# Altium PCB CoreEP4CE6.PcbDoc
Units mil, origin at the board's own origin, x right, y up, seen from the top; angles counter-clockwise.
Board outline 6000 x 4000 mil, 2 copper layers (Top Layer, Bottom Layer); 3 components, 0 nets, 98 pads, 0 vias.
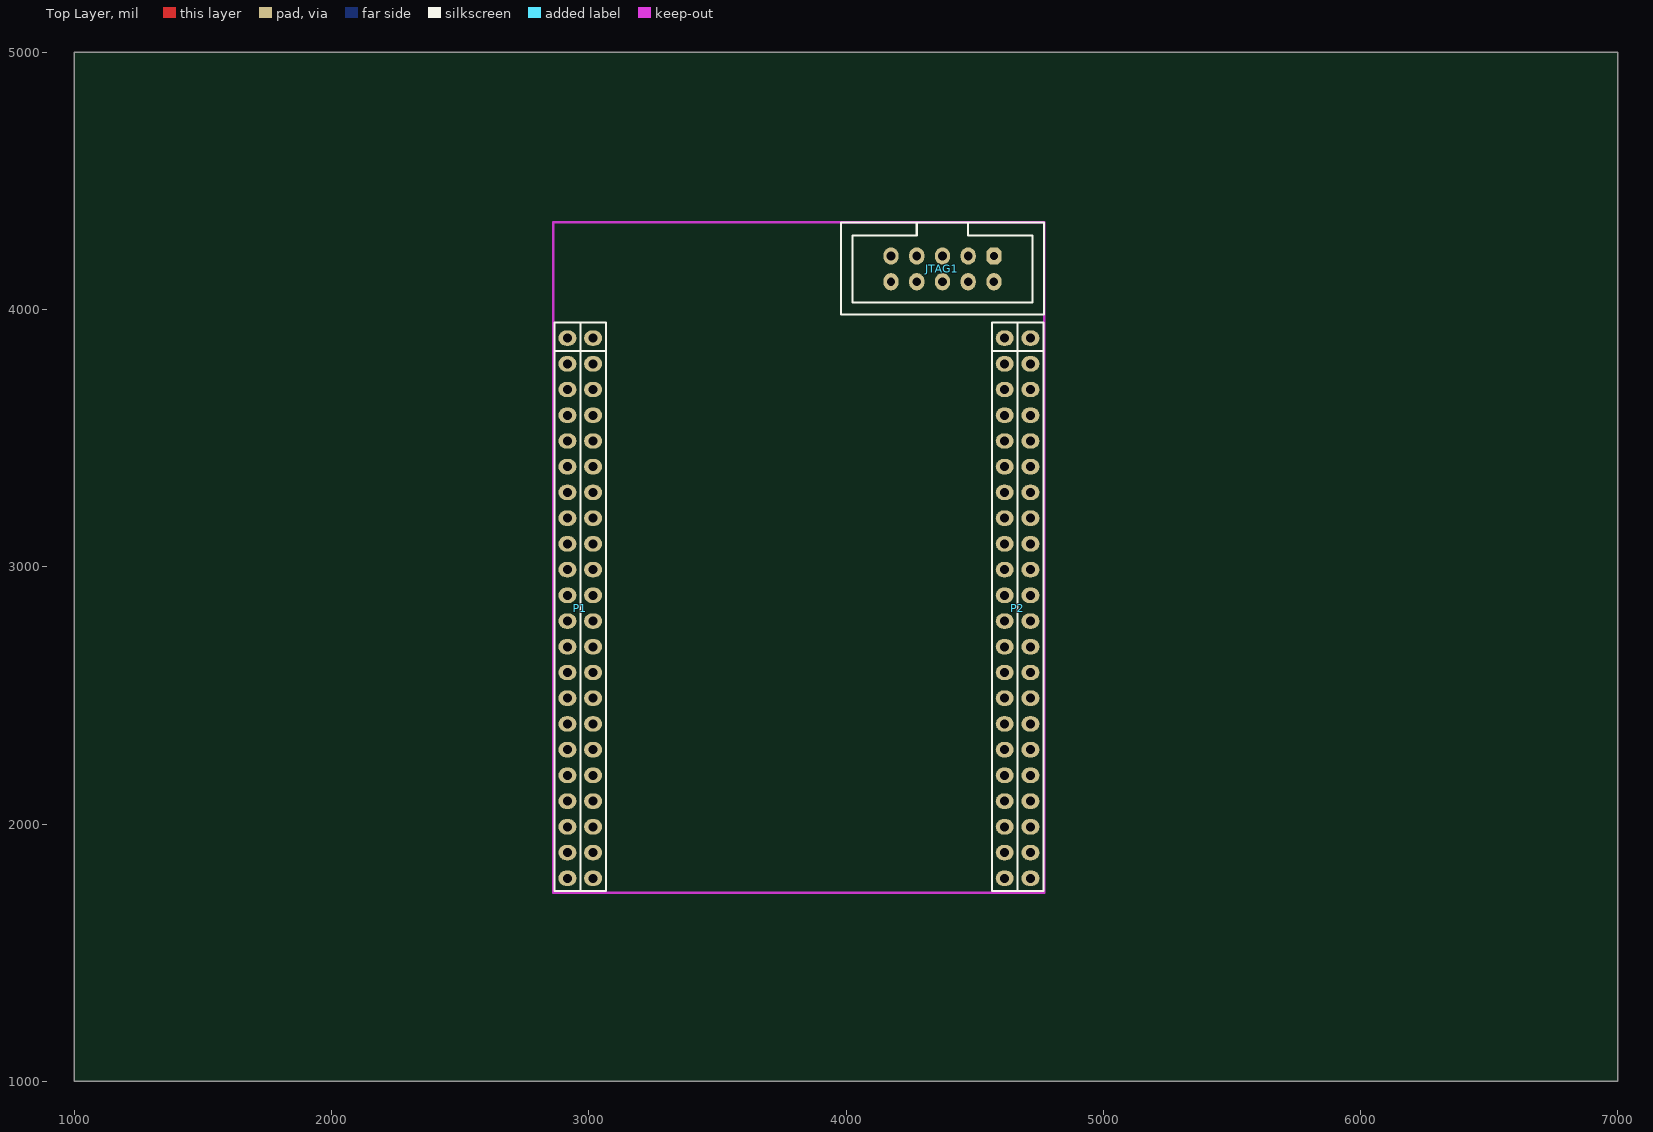
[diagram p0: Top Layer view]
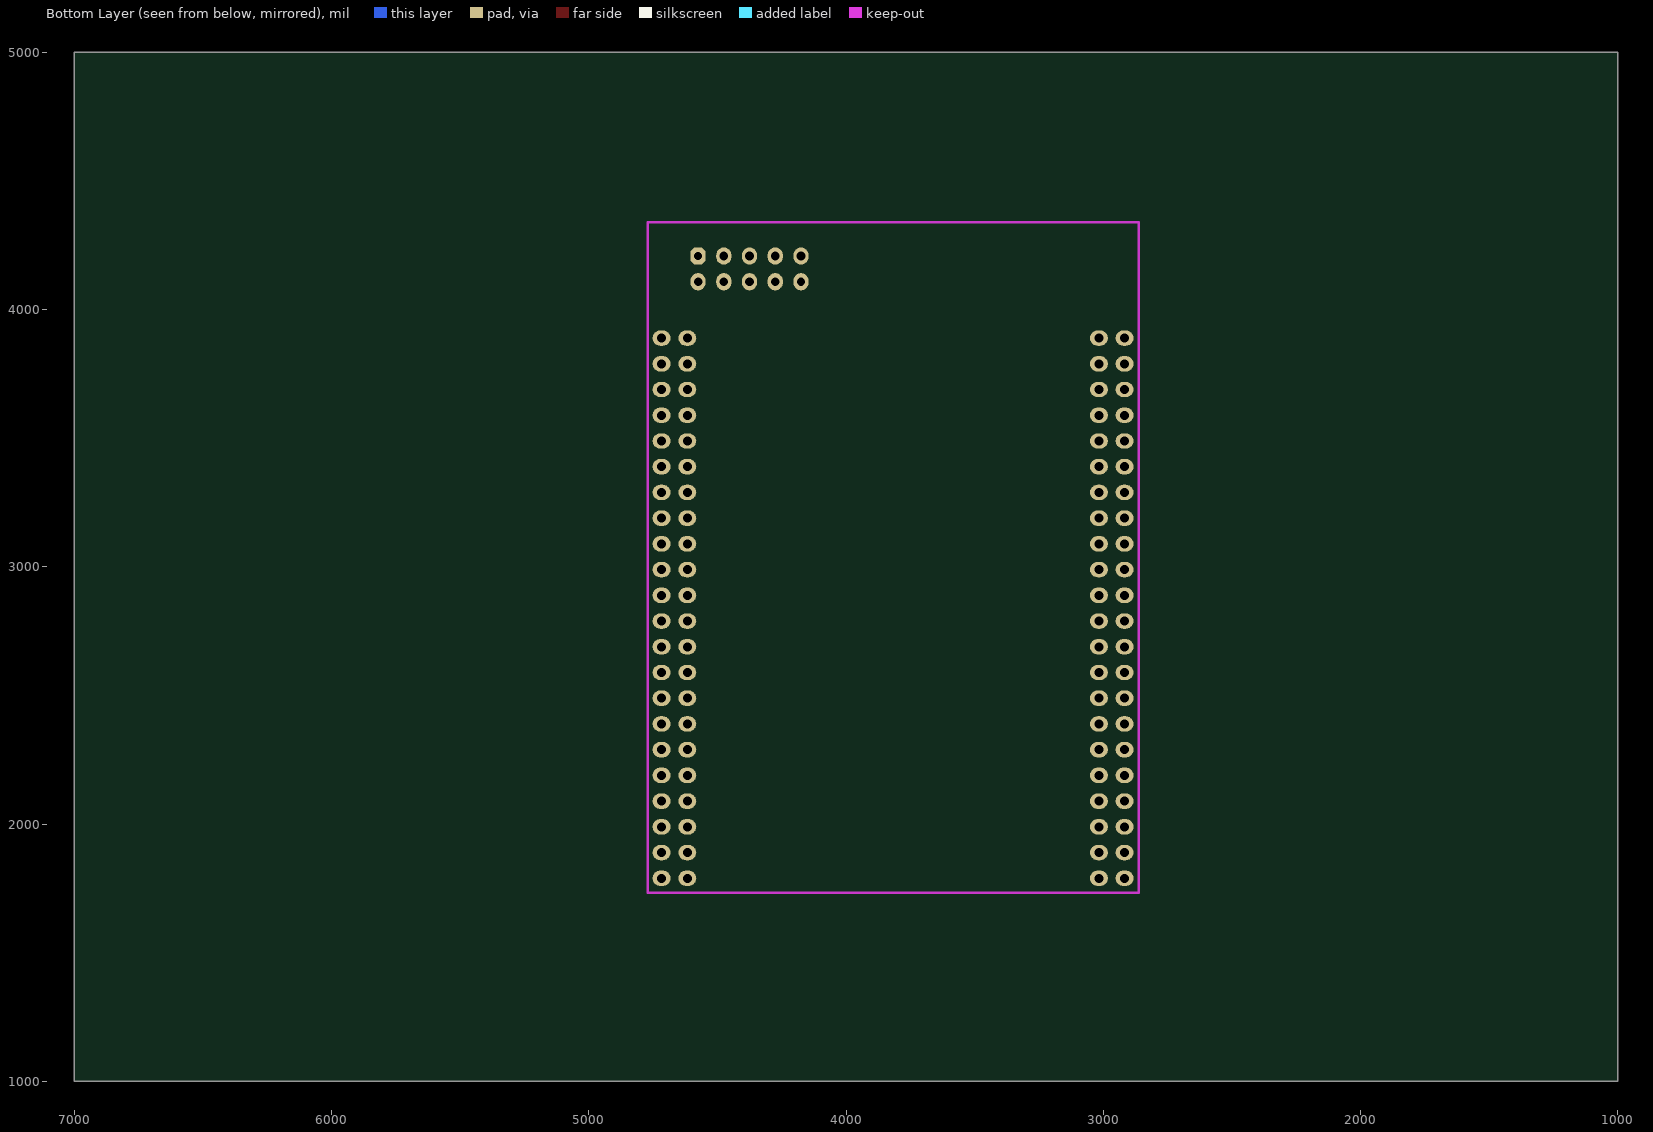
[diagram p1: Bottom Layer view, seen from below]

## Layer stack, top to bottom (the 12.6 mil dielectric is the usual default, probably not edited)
Top Layer: signal copper 1.4
Dielectric: dielectric 12.6, FR-4, Dk 4.8
Bottom Layer: signal copper 1.4

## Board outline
1000,1000 7000,1000 7000,5000 1000,5000

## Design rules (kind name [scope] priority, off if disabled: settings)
Clearance [All] p1: gap=10
PolygonConnect [All] p1: connectstyle=Relief reliefconductorwidth=10 reliefentries=4 polygonreliefangle="90 Angle" airgapwidth=10
RoutingVias [All] p1: holewidth=28 width=50 viastyle="Through Hole" minholewidth=28 minwidth=50 maxholewidth=28 maxwidth=50
SolderMaskExpansion [All] p1: expansion=4
Width [All] p1: maxlimit=10 minlimit=10 preferedwidth=10
28 further rules are at their usual default settings.

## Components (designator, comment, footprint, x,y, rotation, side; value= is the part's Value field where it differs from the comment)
JTAG1 "JTAG" ISP_10 4575,4208 r270 top
P1 "Header 22X2" "Header 22X2" 2917,3889 r0 top
P2 "Header 22X2" "Header 22X2" 4617,3889 r0 top

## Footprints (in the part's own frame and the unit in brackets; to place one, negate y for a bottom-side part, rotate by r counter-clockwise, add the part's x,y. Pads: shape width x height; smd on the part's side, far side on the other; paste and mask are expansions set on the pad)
"Header 22X2" [mil]
  oval 70x60 hole 35: 1(0,0) 2(100,0) 3(0,-100) 4(100,-100) 5(0,-200) 6(100,-200) 7(0,-300) 8(100,-300) 9(0,-400) 10(100,-400) 11(0,-500) 12(100,-500) 13(0,-600) 14(100,-600) 15(0,-700) 16(100,-700) 17(0,-800) 18(100,-800) 19(0,-900) 20(100,-900) 21(0,-1000) 22(100,-1000) 23(0,-1100) 24(100,-1100) 25(0,-1200) 26(100,-1200) 27(0,-1300) 28(100,-1300) 29(0,-1400) 30(100,-1400) 31(0,-1500) 32(100,-1500) 33(0,-1600) 34(100,-1600) 35(0,-1700) 36(100,-1700) 37(0,-1800) 38(100,-1800) 39(0,-1900) 40(100,-1900) 41(0,-2000) 42(100,-2000) 43(0,-2100) 44(100,-2100)
  silkscreen extent -50,-2150 150,60
ISP_10 [mm]
  oct 1.7x1.5 hole 0.8: 1(0,0)
  oval 1.7x1.5 hole 0.85: 2(2.54,0) 3(0,-2.54) 4(2.54,-2.54) 5(0,-5.08) 6(2.54,-5.08) 7(0,-7.62) 8(2.54,-7.62) 9(0,-10.16)
  oval 1.7x1.5 hole 0.8: 10(2.54,-10.16)
  silkscreen extent -3.3,-15.12 5.75,4.95

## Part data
P1 P2: "Header, 22-Pin, Dual row"

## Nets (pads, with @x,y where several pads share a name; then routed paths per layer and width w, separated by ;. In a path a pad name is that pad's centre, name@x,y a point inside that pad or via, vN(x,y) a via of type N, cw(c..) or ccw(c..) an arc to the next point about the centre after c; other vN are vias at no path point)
pads on no net: JTAG1.1 JTAG1.2 JTAG1.3 JTAG1.4 JTAG1.5 JTAG1.6 JTAG1.7 JTAG1.8 JTAG1.9 JTAG1.10 P1.1 P1.2 P1.3 P1.4 P1.5 P1.6 P1.7 P1.8 P1.9 P1.10 P1.11 P1.12 P1.13 P1.14 P1.15 P1.16 P1.17 P1.18 P1.19 P1.20 P1.21 P1.22 P1.23 P1.24 P1.25 P1.26 P1.27 P1.28 P1.29 P1.30 P1.31 P1.32 P1.33 P1.34 P1.35 P1.36 P1.37 P1.38 P1.39 P1.40 P1.41 P1.42 P1.43 P1.44 P2.1 P2.2 P2.3 P2.4 P2.5 P2.6 P2.7 P2.8 P2.9 P2.10 P2.11 P2.12 P2.13 P2.14 P2.15 P2.16 P2.17 P2.18 P2.19 P2.20 P2.21 P2.22 P2.23 P2.24 P2.25 P2.26 P2.27 P2.28 P2.29 P2.30 P2.31 P2.32 P2.33 P2.34 P2.35 P2.36 P2.37 P2.38 P2.39 P2.40 P2.41 P2.42 P2.43 P2.44

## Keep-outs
Keep-Out Layer:
  lines w10: 2862,1733 2862,4339 4770,4339 4770,4222 4770,1733 2862,1733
